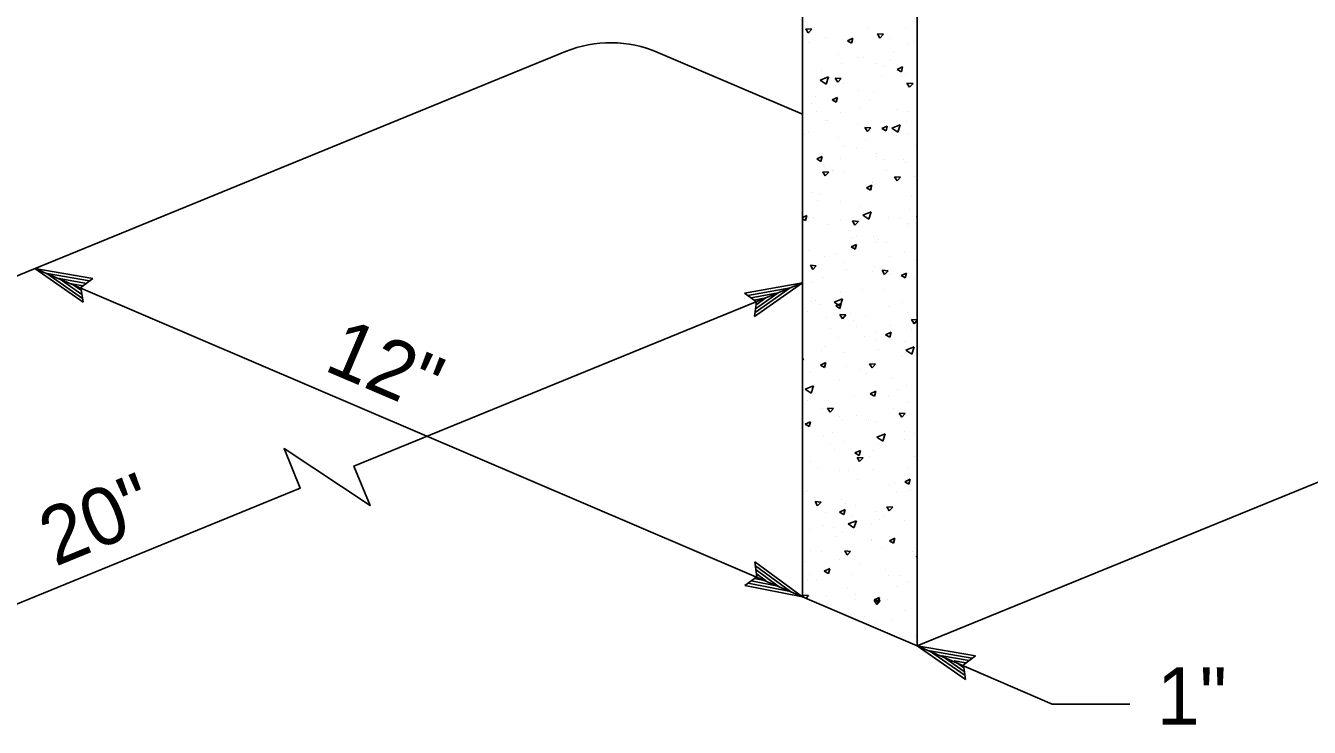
# Model space of a CAD drawing. Extents: x -123486 to -116575, y -107066 to -101122.
# Drawn here: x -117088.2 to -116954.3, y -101483 to -101409.8 of the extents above; entities that cross this region are included whole.
import ezdxf

# ---------------------------------------------------------------- set-up
doc = ezdxf.new("R2010")
doc.units = 0
for name, color, linetype in [('G-MARK', 7, 'Continuous'), ('G-TEXT', 7, 'Continuous'), ('Misc CnstDet(22)', 7, 'Continuous')]:
    doc.layers.add(name, color=color, linetype=linetype)

msp = doc.modelspace()

# ---------------------------------------------------------------- linework, layer by layer
at = {"layer": 'G-MARK'}
msp.add_line((-117087.29, -101435.17), (-117007.18, -101469.41), dxfattribs=at)
for points in [[(-117007.18, -101436.65), (-117053.99, -101455.78), (-117052.3, -101459.9), (-117061.27, -101453.95), (-117059.59, -101458.07), (-117120.68, -101483.05)], [(-116995.2, -101474.53), (-116981.12, -101480.63), (-116973.01, -101480.63)]]:
    msp.add_lwpolyline(points, dxfattribs=at)
at = {"layer": 'G-TEXT'}
for p, q in [((-117082.25, -101438.69), (-117087.29, -101435.17)), ((-117087.29, -101435.17), (-117087.29, -101435.17)), ((-117087.29, -101435.17), (-117081.24, -101436.22)), ((-117082.32, -101438.28), (-117086.02, -101435.69)), ((-117086.01, -101435.69), (-117081.59, -101436.46)), ((-117082.4, -101437.86), (-117084.74, -101436.22)), ((-117084.74, -101436.22), (-117081.89, -101436.71)), ((-117082.43, -101437.47), (-117083.46, -101436.75)), ((-117083.46, -101436.75), (-117082.24, -101436.96)), ((-117081.24, -101436.22), (-117082.48, -101437.14)), ((-117081.24, -101436.22), (-117081.24, -101436.22)), ((-117013.23, -101437.72), (-117007.18, -101436.65)), ((-117007.18, -101436.65), (-117012.2, -101440.18)), ((-117007.18, -101436.65), (-117007.18, -101436.65)), ((-117082.48, -101437.14), (-117082.25, -101438.69)), ((-117011.98, -101438.65), (-117013.23, -101437.72)), ((-117013.23, -101437.72), (-117013.23, -101437.72)), ((-117012.89, -101437.97), (-117008.45, -101437.18)), ((-117012.54, -101438.21), (-117009.73, -101437.71)), ((-117012.24, -101438.46), (-117011, -101438.24)), ((-117008.46, -101437.19), (-117012.12, -101439.76)), ((-117009.73, -101437.71), (-117012.09, -101439.37)), ((-117011, -101438.24), (-117012.02, -101438.95)), ((-117082.25, -101438.69), (-117082.25, -101438.69)), ((-117012.2, -101440.18), (-117011.98, -101438.65)), ((-117012.2, -101440.18), (-117012.2, -101440.18)), ((-117011.94, -101467.33), (-117012.14, -101465.78)), ((-117012.14, -101465.78), (-117012.14, -101465.78)), ((-117012.14, -101465.78), (-117007.18, -101469.41)), ((-117012.08, -101466.2), (-117008.44, -101468.86)), ((-117013.21, -101468.23), (-117011.94, -101467.33)), ((-117009.71, -101468.3), (-117012.55, -101467.75)), ((-117010.97, -101467.75), (-117012.19, -101467.51)), ((-117012.01, -101466.62), (-117009.71, -101468.3)), ((-117011.99, -101467.01), (-117010.97, -101467.75)), ((-117007.18, -101469.41), (-117013.21, -101468.23)), ((-117013.21, -101468.23), (-117013.21, -101468.23)), ((-117008.45, -101468.86), (-117012.85, -101468)), ((-117007.18, -101469.41), (-117007.18, -101469.41)), ((-116990.16, -101478.05), (-116995.2, -101474.53)), ((-116995.2, -101474.53), (-116995.2, -101474.53)), ((-116995.2, -101474.53), (-116989.14, -101475.58)), ((-116990.22, -101477.64), (-116993.92, -101475.06)), ((-116993.91, -101475.06), (-116989.5, -101475.83)), ((-116990.3, -101477.22), (-116992.64, -101475.58)), ((-116992.64, -101475.58), (-116989.79, -101476.08)), ((-116989.14, -101475.58), (-116990.39, -101476.51)), ((-116989.14, -101475.58), (-116989.14, -101475.58)), ((-116990.33, -101476.83), (-116991.37, -101476.11)), ((-116991.37, -101476.11), (-116990.15, -101476.32)), ((-116990.39, -101476.51), (-116990.16, -101478.05)), ((-116990.16, -101478.05), (-116990.16, -101478.05))]:
    msp.add_line(p, q, dxfattribs=at)
at = {"layer": 'Misc CnstDet(22)'}
for p, q in [((-117007.18, -101402.21), (-117007.18, -101469.41)), ((-116995.2, -101407.6), (-116995.2, -101474.53)), ((-117006.85, -101410.16), (-117006.59, -101410.58)), ((-117006.85, -101410.16), (-117006.22, -101410.2)), ((-117005.92, -101410.02), (-117005.92, -101410.02)), ((-117000.35, -101410.13), (-117000.35, -101410.13)), ((-116996.43, -101410.11), (-116996.43, -101410.11)), ((-117006.59, -101410.59), (-117006.22, -101410.2)), ((-117004.78, -101411.05), (-117004.78, -101411.05)), ((-117002.49, -101411.39), (-117001.93, -101411.13)), ((-117002.49, -101411.39), (-117002.06, -101411.64)), ((-117002.06, -101411.64), (-117001.93, -101411.13)), ((-117001.95, -101411.35), (-117001.95, -101411.35)), ((-117001.88, -101411.32), (-117001.88, -101411.32)), ((-116999.37, -101410.68), (-116999.11, -101411.11)), ((-116999.37, -101410.68), (-116998.74, -101410.72)), ((-116999.11, -101411.11), (-116998.74, -101410.72)), ((-116998.12, -101411.11), (-116998.12, -101411.11)), ((-116995.6, -101411.43), (-116995.6, -101411.43)), ((-117120.68, -101448.82), (-117031.92, -101412.53)), ((-117022.28, -101412.61), (-117007.18, -101419.07)), ((-117006.55, -101411.57), (-117006.55, -101411.57)), ((-117003.46, -101412.82), (-117003.46, -101412.82)), ((-116997.69, -101412.58), (-116997.69, -101412.58)), ((-116996.11, -101411.75), (-116996.11, -101411.75)), ((-117003.14, -101413.79), (-117003.14, -101413.79)), ((-117001.49, -101413.17), (-117001.49, -101413.17)), ((-117000.83, -101413.1), (-117000.83, -101413.1)), ((-116999.48, -101413.8), (-116999.48, -101413.8)), ((-116998.7, -101414.12), (-116998.7, -101414.12)), ((-116997.99, -101413.4), (-116997.99, -101413.4)), ((-116997.3, -101414.39), (-116996.73, -101414.13)), ((-116996.86, -101414.64), (-116996.73, -101414.13)), ((-117005.34, -101415.51), (-117004.46, -101415.17)), ((-117005.34, -101415.51), (-117004.71, -101415.93)), ((-117005.24, -101414.49), (-117005.24, -101414.49)), ((-117004.87, -101415.22), (-117004.87, -101415.22)), ((-117004.71, -101415.93), (-117004.46, -101415.17)), ((-117003.76, -101415.3), (-117003.5, -101415.73)), ((-117003.76, -101415.3), (-117003.13, -101415.34)), ((-117003.5, -101415.73), (-117003.13, -101415.34)), ((-116998.96, -101415.05), (-116998.96, -101415.05)), ((-116997.3, -101414.39), (-116996.86, -101414.64)), ((-116996.88, -101415.16), (-116996.88, -101415.16)), ((-116996.45, -101414.76), (-116996.45, -101414.76)), ((-117004.41, -101416.26), (-117004.41, -101416.26)), ((-117002.86, -101415.85), (-117002.86, -101415.85)), ((-117001.29, -101416.54), (-117001.29, -101416.54)), ((-116999.82, -101416.81), (-116999.82, -101416.81)), ((-116996.28, -101415.82), (-116996.02, -101416.25)), ((-116996.28, -101415.82), (-116995.65, -101415.87)), ((-116996.02, -101416.25), (-116995.65, -101415.87)), ((-117006.24, -101417.9), (-117006.24, -101417.9)), ((-117005.87, -101417.18), (-117005.87, -101417.18)), ((-117004.09, -101417.56), (-117003.53, -101417.3)), ((-117004.09, -101417.56), (-117003.66, -101417.81)), ((-117003.66, -101417.81), (-117003.53, -101417.3)), ((-117000.22, -101417.52), (-117000.22, -101417.52)), ((-117005.67, -101418.73), (-117005.67, -101418.73)), ((-117003.2, -101418.86), (-117003.2, -101418.86)), ((-117001.11, -101418.48), (-117001.11, -101418.48)), ((-116997.34, -101418.59), (-116997.34, -101418.59)), ((-116996.09, -101418.8), (-116996.09, -101418.8)), ((-117004.83, -101419.69), (-117004.83, -101419.69)), ((-117004.56, -101419.71), (-117004.56, -101419.71)), ((-117001.48, -101420), (-117001.48, -101420)), ((-117000.67, -101420.44), (-117000.41, -101420.87)), ((-117000.67, -101420.44), (-117000.04, -101420.48)), ((-117000.41, -101420.87), (-117000.04, -101420.49)), ((-116998.9, -101420.56), (-116998.33, -101420.3)), ((-116998.9, -101420.56), (-116998.46, -101420.81)), ((-116998.46, -101420.81), (-116998.33, -101420.3)), ((-116998.14, -101420.46), (-116998.14, -101420.46)), ((-116997.86, -101420.52), (-116996.99, -101420.18)), ((-116997.86, -101420.52), (-116997.24, -101420.94)), ((-116997.24, -101420.94), (-116996.99, -101420.18)), ((-116996.36, -101419.78), (-116996.36, -101419.78)), ((-117006.94, -101421.2), (-117006.94, -101421.2)), ((-117006.58, -101420.91), (-117006.58, -101420.91)), ((-117003.44, -101421.47), (-117003.44, -101421.47)), ((-117000.61, -101421.76), (-117000.61, -101421.76)), ((-117000.08, -101420.98), (-117000.08, -101420.98)), ((-116997.36, -101421.27), (-116997.36, -101421.27)), ((-116996.13, -101421.09), (-116996.13, -101421.09)), ((-117005.7, -101423.73), (-117005.13, -101423.47)), ((-117005.26, -101423.98), (-117005.13, -101423.47)), ((-117002.75, -101422.47), (-117002.75, -101422.47)), ((-117001.51, -101422.51), (-117001.51, -101422.51)), ((-116999.51, -101423.14), (-116999.51, -101423.14)), ((-116999.49, -101423.52), (-116999.49, -101423.52)), ((-116995.32, -101422.28), (-116995.32, -101422.28)), ((-117005.7, -101423.73), (-117005.26, -101423.98)), ((-117004.89, -101424.56), (-117004.89, -101424.56)), ((-117003.9, -101424.9), (-117003.9, -101424.9)), ((-117003.18, -101423.67), (-117003.18, -101423.67)), ((-116998.62, -101423.74), (-116998.62, -101423.74)), ((-116996.65, -101423.81), (-116996.65, -101423.81)), ((-116996.47, -101424.1), (-116996.47, -101424.1)), ((-117005.06, -101425.06), (-117004.8, -101425.49)), ((-117005.06, -101425.06), (-117004.43, -101425.1)), ((-117004.8, -101425.49), (-117004.43, -101425.11)), ((-117004.01, -101424.94), (-117004.01, -101424.94)), ((-117002.88, -101425.19), (-117002.88, -101425.19)), ((-116999.89, -101426.21), (-116999.89, -101426.21)), ((-116999.85, -101426.15), (-116999.85, -101426.15)), ((-116998.43, -101424.97), (-116998.43, -101424.97)), ((-116997.58, -101425.58), (-116997.32, -101426.01)), ((-116997.58, -101425.58), (-116996.95, -101425.63)), ((-116997.32, -101426.02), (-116996.95, -101425.63)), ((-116995.53, -101425.57), (-116995.53, -101425.57)), ((-117006.26, -101427.25), (-117006.26, -101427.25)), ((-117005.28, -101427.41), (-117005.28, -101427.41)), ((-117000.5, -101426.73), (-116999.93, -101426.47)), ((-117000.5, -101426.73), (-117000.07, -101426.98)), ((-117000.07, -101426.98), (-116999.93, -101426.47)), ((-116999.95, -101426.95), (-116999.95, -101426.95)), ((-116995.85, -101427.51), (-116995.85, -101427.51)), ((-117007.17, -101428.07), (-117007.17, -101428.07)), ((-117005.6, -101428.04), (-117005.6, -101428.04)), ((-117003.22, -101428.2), (-117003.22, -101428.2)), ((-117001.15, -101428.69), (-117001.15, -101428.69)), ((-117007.18, -101429.84), (-117006.73, -101429.64)), ((-117007.18, -101429.97), (-117006.86, -101430.15)), ((-117006.86, -101430.15), (-117006.73, -101429.64)), ((-117006.6, -101430.26), (-117006.6, -101430.26)), ((-117006.54, -101429.88), (-117006.54, -101429.88)), ((-117006.05, -101429.83), (-117006.05, -101429.83)), ((-117003.22, -101430.12), (-117003.22, -101430.12)), ((-117001.97, -101430.2), (-117001.71, -101430.63)), ((-117001.97, -101430.2), (-117001.34, -101430.25)), ((-117001.71, -101430.64), (-117001.34, -101430.25)), ((-117000.87, -101429.59), (-117000, -101429.25)), ((-117000.87, -101429.59), (-117000.25, -101430.01)), ((-117000.84, -101429.33), (-117000.84, -101429.33)), ((-117000.25, -101430.01), (-117000, -101429.26)), ((-116998.16, -101429.8), (-116998.16, -101429.8)), ((-116997.11, -101429.98), (-116997.11, -101429.98)), ((-116995.99, -101429), (-116995.99, -101429)), ((-116995.3, -101429.73), (-116995.2, -101429.68)), ((-116995.3, -101429.73), (-116995.2, -101429.79)), ((-117004.56, -101430.54), (-117004.56, -101430.54)), ((-117002.42, -101431.16), (-117002.42, -101431.16)), ((-116996.15, -101430.43), (-116996.15, -101430.43)), ((-116996.08, -101430.63), (-116996.08, -101430.63)), ((-117002.1, -101431.88), (-117002.1, -101431.88)), ((-117002.1, -101432.9), (-117001.53, -101432.64)), ((-117002.1, -101432.9), (-117001.67, -101433.15)), ((-117001.67, -101433.15), (-117001.53, -101432.64)), ((-117001.54, -101431.85), (-117001.54, -101431.85)), ((-116999.8, -101431.84), (-116999.8, -101431.84)), ((-116999.53, -101432.48), (-116999.53, -101432.48)), ((-116999.26, -101432.17), (-116999.26, -101432.17)), ((-116998.37, -101432.45), (-116998.37, -101432.45)), ((-117006.51, -101433.26), (-117006.51, -101433.26)), ((-117004.91, -101433.9), (-117004.91, -101433.9)), ((-117003.68, -101433.63), (-117003.68, -101433.63)), ((-116998.14, -101433.93), (-116998.14, -101433.93)), ((-116996.49, -101433.44), (-116996.49, -101433.44)), ((-116995.31, -101434.22), (-116995.31, -101434.22)), ((-117006.36, -101434.82), (-117006.1, -101435.25)), ((-117006.36, -101434.82), (-117005.74, -101434.87)), ((-117006.1, -101435.25), (-117005.74, -101434.87)), ((-117002.91, -101434.53), (-117002.91, -101434.53)), ((-117002.9, -101434.54), (-117002.9, -101434.54)), ((-117002.56, -101435.31), (-117002.56, -101435.31)), ((-116999.87, -101435.49), (-116999.87, -101435.49)), ((-116999.64, -101434.92), (-116999.64, -101434.92)), ((-116998.88, -101435.35), (-116998.62, -101435.78)), ((-116998.88, -101435.35), (-116998.25, -101435.39)), ((-116998.62, -101435.78), (-116998.25, -101435.39)), ((-116996.9, -101435.9), (-116996.34, -101435.64)), ((-116996.47, -101436.15), (-116996.34, -101435.64)), ((-117006.28, -101436.59), (-117006.28, -101436.59)), ((-117004.94, -101436.1), (-117004.94, -101436.1)), ((-116998.15, -101435.82), (-116998.15, -101435.82)), ((-116996.9, -101435.9), (-116996.47, -101436.15)), ((-116995.45, -101436.19), (-116995.45, -101436.19)), ((-117003.24, -101437.55), (-117003.24, -101437.55)), ((-117000.9, -101437.4), (-117000.9, -101437.4)), ((-116998.6, -101437.36), (-116998.6, -101437.36)), ((-117006.62, -101439.6), (-117006.62, -101439.6)), ((-117006.21, -101438.57), (-117006.21, -101438.57)), ((-117005.83, -101438.48), (-117005.83, -101438.48)), ((-117005.32, -101438.89), (-117005.32, -101438.89)), ((-117003.88, -101438.67), (-117003.01, -101438.33)), ((-117003.88, -101438.67), (-117003.26, -101439.08)), ((-117003.7, -101439.07), (-117003.13, -101438.81)), ((-117003.7, -101439.07), (-117003.27, -101439.32)), ((-117003.27, -101439.32), (-117003.13, -101438.81)), ((-117003.26, -101439.09), (-117003.01, -101438.33)), ((-116998.18, -101439.14), (-116998.18, -101439.14)), ((-116996.72, -101438.66), (-116996.72, -101438.66)), ((-117004.71, -101440.24), (-117004.71, -101440.24)), ((-117003.27, -101439.97), (-117003.01, -101440.4)), ((-117003.27, -101439.97), (-117002.65, -101440.01)), ((-117003.01, -101440.4), (-117002.65, -101440.01)), ((-117002.17, -101439.87), (-117002.17, -101439.87)), ((-117001.88, -101440.54), (-117001.88, -101440.54)), ((-117000.56, -101440.18), (-117000.56, -101440.18)), ((-116996.18, -101439.78), (-116996.18, -101439.78)), ((-116995.79, -101440.49), (-116995.53, -101440.92)), ((-116995.79, -101440.49), (-116995.2, -101440.53)), ((-116995.53, -101440.92), (-116995.2, -101440.57)), ((-117004.28, -101441.39), (-117004.28, -101441.39)), ((-117001.56, -101441.19), (-117001.56, -101441.19)), ((-117000.76, -101442.29), (-117000.76, -101442.29)), ((-116999.55, -101441.83), (-116999.55, -101441.83)), ((-116998.51, -101442.07), (-116997.94, -101441.81)), ((-116998.51, -101442.07), (-116998.07, -101442.32)), ((-116998.07, -101442.32), (-116997.94, -101441.81)), ((-116997.98, -101441.13), (-116997.98, -101441.13)), ((-116995.81, -101441.48), (-116995.81, -101441.48)), ((-117005.17, -101443.67), (-117005.17, -101443.67)), ((-117004.93, -101443.25), (-117004.93, -101443.25)), ((-117003.43, -101442.34), (-117003.43, -101442.34)), ((-116999.53, -101442.69), (-116999.53, -101442.69)), ((-116999.25, -101443.6), (-116999.25, -101443.6)), ((-116997.92, -101442.59), (-116997.92, -101442.59)), ((-116996.52, -101442.78), (-116996.52, -101442.78)), ((-116996.41, -101443.67), (-116995.53, -101443.34)), ((-116996.41, -101443.67), (-116995.78, -101444.09)), ((-116995.78, -101444.09), (-116995.53, -101443.34)), ((-117007.18, -101444.62), (-117007.04, -101444.63)), ((-117007.18, -101444.78), (-117007.04, -101444.63)), ((-117005.3, -101445.24), (-117004.74, -101444.98)), ((-117004.87, -101445.49), (-117004.74, -101444.98)), ((-117004.7, -101444.81), (-117004.7, -101444.81)), ((-117002.93, -101443.88), (-117002.93, -101443.88)), ((-116999.89, -101444.84), (-116999.89, -101444.84)), ((-116996.8, -101444.34), (-116996.8, -101444.34)), ((-117006.3, -101445.93), (-117006.3, -101445.93)), ((-117005.3, -101445.24), (-117004.87, -101445.49)), ((-117002.63, -101445.38), (-117002.63, -101445.38)), ((-117001.22, -101445.72), (-117001.22, -101445.72)), ((-117000.51, -101446.07), (-117000.51, -101446.07)), ((-117000.18, -101445.11), (-116999.92, -101445.54)), ((-117000.18, -101445.11), (-116999.56, -101445.15)), ((-116999.92, -101445.54), (-116999.55, -101445.16)), ((-117006.9, -101447.74), (-117006.02, -101447.4)), ((-117006.27, -101448.16), (-117006.02, -101447.4)), ((-117005.96, -101447.28), (-117005.96, -101447.28)), ((-117003.27, -101446.89), (-117003.27, -101446.89)), ((-116997.88, -101446.68), (-116997.88, -101446.68)), ((-116996.38, -101447.35), (-116996.38, -101447.35)), ((-117006.9, -101447.74), (-117006.27, -101448.16)), ((-117006.64, -101448.94), (-117006.64, -101448.94)), ((-117004.49, -101448.9), (-117004.49, -101448.9)), ((-117001.77, -101448.54), (-117001.77, -101448.54)), ((-117000.11, -101448.24), (-116999.54, -101447.98)), ((-117000.11, -101448.24), (-116999.67, -101448.49)), ((-116999.67, -101448.49), (-116999.54, -101447.98)), ((-116998.2, -101448.49), (-116998.2, -101448.49)), ((-116997.26, -101447.77), (-116997.26, -101447.77)), ((-117005.05, -101449.74), (-117005.05, -101449.74)), ((-117004.57, -101449.73), (-117004.31, -101450.16)), ((-117004.57, -101449.73), (-117003.95, -101449.77)), ((-117004.31, -101450.16), (-117003.95, -101449.78)), ((-116997.65, -101449.82), (-116997.65, -101449.82)), ((-116997.09, -101450.25), (-116996.83, -101450.68)), ((-116997.09, -101450.25), (-116996.47, -101450.3)), ((-116996.83, -101450.68), (-116996.46, -101450.3)), ((-116996.2, -101449.12), (-116996.2, -101449.12)), ((-117006.9, -101451.41), (-117006.34, -101451.15)), ((-117006.9, -101451.41), (-117006.47, -101451.66)), ((-117006.47, -101451.66), (-117006.34, -101451.15)), ((-117003.37, -101450.65), (-117003.37, -101450.65)), ((-117003.04, -101451.02), (-117003.04, -101451.02)), ((-117001.58, -101450.54), (-117001.58, -101450.54)), ((-117000.53, -101450.95), (-117000.53, -101450.95)), ((-117000.29, -101451.04), (-117000.29, -101451.04)), ((-116999.57, -101451.17), (-116999.57, -101451.17)), ((-116995.2, -101474.53), (-116937.72, -101451.04)), ((-117004.96, -101452.59), (-117004.96, -101452.59)), ((-117004.01, -101452.24), (-117004.01, -101452.24)), ((-116999.42, -101452.75), (-116998.55, -101452.41)), ((-116999.42, -101452.75), (-116998.8, -101453.17)), ((-116999.41, -101452.7), (-116999.41, -101452.7)), ((-116998.91, -101452.29), (-116998.91, -101452.29)), ((-116998.8, -101453.17), (-116998.54, -101452.41)), ((-116996.58, -101453), (-116996.58, -101453)), ((-116996.54, -101452.13), (-116996.54, -101452.13)), ((-116995.53, -101452.33), (-116995.53, -101452.33)), ((-117004.3, -101453.49), (-117004.3, -101453.49)), ((-117003.83, -101454.09), (-117003.83, -101454.09)), ((-117002.95, -101453.22), (-117002.95, -101453.22)), ((-117001.71, -101454.41), (-117001.14, -101454.15)), ((-117001.27, -101454.66), (-117001.14, -101454.15)), ((-116999.91, -101454.18), (-116999.91, -101454.18)), ((-116999.25, -101453.54), (-116999.25, -101453.54)), ((-117007.11, -101454.93), (-117007.11, -101454.93)), ((-117006.33, -101455.28), (-117006.33, -101455.28)), ((-117001.71, -101454.41), (-117001.27, -101454.66)), ((-117001.48, -101454.87), (-117001.22, -101455.3)), ((-117001.48, -101454.87), (-117000.86, -101454.92)), ((-117001.22, -101455.3), (-117000.86, -101454.92)), ((-117000.18, -101454.76), (-117000.18, -101454.76)), ((-116995.46, -101454.76), (-116995.46, -101454.76)), ((-117005.57, -101455.96), (-117005.57, -101455.96)), ((-117003.29, -101456.23), (-117003.29, -101456.23)), ((-117002.36, -101456.23), (-117002.36, -101456.23)), ((-116999.87, -101456.14), (-116999.87, -101456.14)), ((-116996.14, -101456.06), (-116996.14, -101456.06)), ((-117007.1, -101457.26), (-117007.1, -101457.26)), ((-117006.67, -101458.29), (-117006.67, -101458.29)), ((-117001.44, -101457.23), (-117001.44, -101457.23)), ((-116998.23, -101457.83), (-116998.23, -101457.83)), ((-116997.6, -101457.53), (-116997.6, -101457.53)), ((-116996.51, -101457.41), (-116995.94, -101457.15)), ((-116996.51, -101457.41), (-116996.08, -101457.66)), ((-116996.08, -101457.66), (-116995.94, -101457.15)), ((-116995.92, -101458.19), (-116995.92, -101458.19)), ((-117006.83, -101458.43), (-117006.83, -101458.43)), ((-117005.98, -101459.02), (-117005.98, -101459.02)), ((-117005.87, -101459.49), (-117005.61, -101459.92)), ((-117005.87, -101459.49), (-117005.25, -101459.54)), ((-117005.61, -101459.92), (-117005.25, -101459.54)), ((-117003.14, -101459.31), (-117003.14, -101459.31)), ((-117002.7, -101459.71), (-117002.7, -101459.71)), ((-116997.4, -101458.53), (-116997.4, -101458.53)), ((-116996.22, -101458.46), (-116996.22, -101458.46)), ((-117004.77, -101460.59), (-117004.77, -101460.59)), ((-117003.31, -101460.58), (-117002.74, -101460.31)), ((-117003.31, -101460.58), (-117002.88, -101460.83)), ((-117002.88, -101460.83), (-117002.74, -101460.32)), ((-117002.03, -101461.07), (-117002.03, -101461.07)), ((-117001.6, -101459.88), (-117001.6, -101459.88)), ((-116999.6, -101460.51), (-116999.6, -101460.51)), ((-116998.66, -101461), (-116998.66, -101461)), ((-116998.39, -101460.02), (-116998.13, -101460.44)), ((-116998.39, -101460.02), (-116997.77, -101460.06)), ((-116998.13, -101460.45), (-116997.77, -101460.06)), ((-117004.98, -101461.93), (-117004.98, -101461.93)), ((-117003.97, -101462.18), (-117003.97, -101462.18)), ((-117002.43, -101461.82), (-117001.56, -101461.48)), ((-117002.43, -101461.82), (-117001.81, -101462.24)), ((-117001.81, -101462.24), (-117001.56, -101461.49)), ((-117000.01, -101461.89), (-117000.01, -101461.89)), ((-116999.19, -101461.36), (-116999.19, -101461.36)), ((-116996.56, -101461.47), (-116996.56, -101461.47)), ((-117006.44, -101462.45), (-117006.44, -101462.45)), ((-117003.73, -101463.09), (-117003.73, -101463.09)), ((-117002.97, -101462.57), (-117002.97, -101462.57)), ((-116999.94, -101463.52), (-116999.94, -101463.52)), ((-116999.93, -101463.47), (-116999.93, -101463.47)), ((-116998.11, -101463.58), (-116997.55, -101463.31)), ((-116998.11, -101463.58), (-116997.68, -101463.83)), ((-116998.07, -101463.12), (-116998.07, -101463.12)), ((-116997.68, -101463.83), (-116997.55, -101463.32)), ((-116995.26, -101463.19), (-116995.26, -101463.19)), ((-116995.24, -101463.41), (-116995.24, -101463.41)), ((-117006.35, -101464.62), (-117006.35, -101464.62)), ((-117005.23, -101464.65), (-117005.23, -101464.65)), ((-117002.78, -101464.64), (-117002.52, -101465.06)), ((-117002.78, -101464.64), (-117002.16, -101464.68)), ((-117002.52, -101465.07), (-117002.16, -101464.68)), ((-117002.49, -101464.5), (-117002.49, -101464.5)), ((-116998.98, -101464.39), (-116998.98, -101464.39)), ((-116995.74, -101464.74), (-116995.74, -101464.74)), ((-117006.84, -101465.78), (-117006.84, -101465.78)), ((-117003.31, -101465.58), (-117003.31, -101465.58)), ((-117001.19, -101465.94), (-117001.19, -101465.94)), ((-116995.3, -101465.16), (-116995.2, -101465.33)), ((-116995.3, -101465.16), (-116995.2, -101465.17)), ((-117006.69, -101467.63), (-117006.69, -101467.63)), ((-117006.5, -101467.12), (-117006.5, -101467.12)), ((-117005.76, -101467.67), (-117005.76, -101467.67)), ((-117004.91, -101466.75), (-117004.34, -101466.48)), ((-117004.91, -101466.75), (-117004.48, -101467)), ((-117004.48, -101467), (-117004.34, -101466.49)), ((-117002.08, -101467.08), (-117002.08, -101467.08)), ((-116998.53, -101466.55), (-116998.53, -101466.55)), ((-116998.25, -101467.17), (-116998.25, -101467.17)), ((-116997.01, -101467.21), (-116997.01, -101467.21)), ((-117002.46, -101468.42), (-117002.46, -101468.42)), ((-116997.33, -101468.38), (-116997.33, -101468.38)), ((-116996.24, -101467.8), (-116996.24, -101467.8)), ((-117007.18, -101469.41), (-116995.2, -101474.53)), ((-117007.17, -101469.26), (-117007.05, -101469.47)), ((-117007.17, -101469.26), (-117006.55, -101469.3)), ((-117006.8, -101469.57), (-117006.55, -101469.3)), ((-117004.64, -101469.43), (-117004.64, -101469.43)), ((-117001.8, -101469.72), (-117001.8, -101469.72)), ((-117001.62, -101469.22), (-117001.62, -101469.22)), ((-116999.71, -101469.75), (-116999.15, -101469.48)), ((-116999.71, -101469.75), (-116999.28, -101470)), ((-116999.69, -101469.78), (-116999.43, -101470.21)), ((-116999.69, -101469.78), (-116999.07, -101469.82)), ((-116999.62, -101469.86), (-116999.62, -101469.86)), ((-116999.43, -101470.21), (-116999.07, -101469.82)), ((-116999.28, -101470), (-116999.15, -101469.49)), ((-116998.27, -101469.68), (-116998.27, -101469.68)), ((-117003.72, -101470.89), (-117003.72, -101470.89)), ((-117000.68, -101471.48), (-117000.68, -101471.48)), ((-116997.85, -101471.77), (-116997.85, -101471.77)), ((-116996.58, -101470.81), (-116996.58, -101470.81)), ((-116999.53, -101472.15), (-116999.53, -101472.15)), ((-116996.73, -101473.53), (-116996.73, -101473.53)), ((-116995.41, -101473.43), (-116995.41, -101473.43))]:
    msp.add_line(p, q, dxfattribs=at)
msp.add_arc((-117027.19, -101424.1), 12.5, 66.8572, 112.2327, dxfattribs=at)

# ---------------------------------------------------------------- texts
for s, rotation, p in [('12"', 336.8572, (-117057.27, -101445.72)), ('20"', 22.2327, (-117085.17, -101466.31))]:
    msp.add_text(s, height=6, rotation=rotation, dxfattribs=at).set_placement(p)
msp.add_text('1"', height=6, dxfattribs=at).set_placement((-116970.2, -101482.78))

doc.saveas('drawing.dxf')
